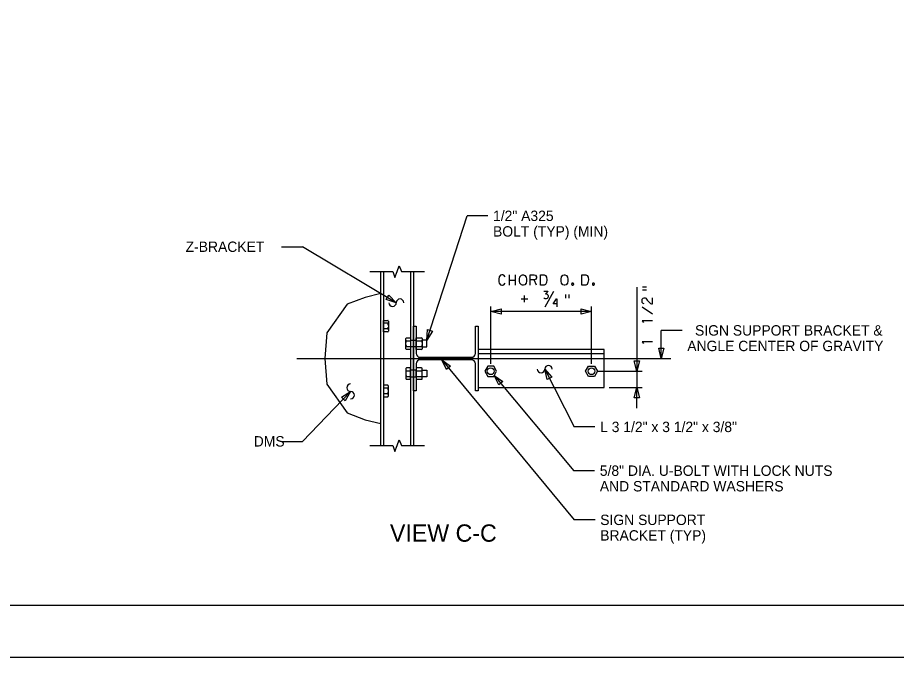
# Model space of a CAD drawing. Extents: x 3831399 to 3833095, y 499014 to 500202.
# Drawn here: x 3832543.5 to 3832797.3, y 499014 to 499198.8 of the extents above; entities that cross this region are included whole.
import ezdxf

# ---------------------------------------------------------------- set-up
doc = ezdxf.new("R2010")
doc.units = 0
for name, color, linetype in [('0-ANCHOR', 7, 'Continuous'), ('2', 7, 'Continuous'), ('CNTR', 7, 'Continuous'), ('Default', 7, 'Continuous'), ('DIM TXT', 7, 'Continuous'), ('PLT-BNDY', 7, 'Continuous'), ('sign', 7, 'Continuous'), ('structure', 7, 'Continuous')]:
    doc.layers.add(name, color=color, linetype=linetype)

msp = doc.modelspace()

# ---------------------------------------------------------------- linework, layer by layer
at = {"layer": '0-ANCHOR'}
for p, q in [((3832649.19, 499108.06), (3832649.19, 499111.38)), ((3832649.19, 499111.38), (3832650.37, 499111.38)), ((3832650.37, 499110.55), (3832649.19, 499110.55)), ((3832650.56, 499111.19), (3832650.56, 499108.25)), ((3832650.37, 499108.89), (3832649.19, 499108.89)), ((3832650.37, 499108.06), (3832649.19, 499108.06)), ((3832655.63, 499103.2), (3832655.63, 499106.15)), ((3832655.82, 499106.34), (3832657, 499106.34)), ((3832655.82, 499105.5), (3832657, 499105.5)), ((3832657, 499106.34), (3832657, 499103.01)), ((3832657, 499105.65), (3832658.59, 499105.65)), ((3832658.59, 499103.01), (3832658.59, 499106.34)), ((3832658.59, 499106.34), (3832660.17, 499106.34)), ((3832658.59, 499105.65), (3832658.59, 499103.7)), ((3832658.59, 499105.5), (3832660.17, 499105.5)), ((3832660.35, 499106.15), (3832660.35, 499103.2)), ((3832661.7, 499105.65), (3832660.35, 499105.65)), ((3832661.7, 499103.7), (3832661.7, 499105.65)), ((3832655.82, 499103.84), (3832657, 499103.84)), ((3832657, 499103.01), (3832655.82, 499103.01)), ((3832658.59, 499103.7), (3832657, 499103.7)), ((3832658.59, 499103.84), (3832660.17, 499103.84)), ((3832660.17, 499103.01), (3832658.59, 499103.01)), ((3832660.35, 499103.7), (3832661.7, 499103.7)), ((3832655.63, 499097.49), (3832655.63, 499094.55)), ((3832657, 499097.68), (3832655.82, 499097.68)), ((3832655.82, 499096.85), (3832657, 499096.85)), ((3832657, 499094.36), (3832657, 499097.68)), ((3832658.59, 499097), (3832657, 499097)), ((3832660.17, 499097.68), (3832658.59, 499097.68)), ((3832658.59, 499097.68), (3832658.59, 499094.36)), ((3832658.59, 499095.04), (3832658.59, 499097)), ((3832658.59, 499096.85), (3832660.17, 499096.85)), ((3832660.35, 499094.55), (3832660.35, 499097.49)), ((3832660.35, 499097), (3832661.7, 499097)), ((3832661.7, 499097), (3832661.7, 499095.04)), ((3832679.26, 499098.17), (3832678.4, 499096.69)), ((3832678.4, 499096.69), (3832679.26, 499095.21)), ((3832680.97, 499098.17), (3832679.26, 499098.17)), ((3832681.82, 499096.69), (3832680.97, 499098.17)), ((3832680.97, 499095.21), (3832681.82, 499096.69)), ((3832707.51, 499096.69), (3832708.36, 499098.17)), ((3832708.36, 499095.21), (3832707.51, 499096.69)), ((3832708.36, 499098.17), (3832710.07, 499098.17)), ((3832710.07, 499098.17), (3832710.92, 499096.69)), ((3832710.92, 499096.69), (3832710.07, 499095.21)), ((3832655.82, 499095.19), (3832657, 499095.19)), ((3832655.82, 499094.36), (3832657, 499094.36)), ((3832657, 499095.04), (3832658.59, 499095.04)), ((3832658.59, 499095.19), (3832660.17, 499095.19)), ((3832658.59, 499094.36), (3832660.17, 499094.36)), ((3832661.7, 499095.04), (3832660.35, 499095.04)), ((3832679.26, 499095.21), (3832680.97, 499095.21)), ((3832710.07, 499095.21), (3832708.36, 499095.21)), ((3832650.37, 499092.63), (3832649.19, 499092.63)), ((3832649.19, 499092.63), (3832649.19, 499089.31)), ((3832650.37, 499091.8), (3832649.19, 499091.8)), ((3832650.56, 499089.5), (3832650.56, 499092.44)), ((3832650.37, 499090.14), (3832649.19, 499090.14)), ((3832649.19, 499089.31), (3832650.37, 499089.31))]:
    msp.add_line(p, q, dxfattribs=at)
for centre in [(3832680.11, 499096.69), (3832709.21, 499096.69)]:
    msp.add_circle(centre, 0.977, dxfattribs=at)
for centre, start, end in [((3832650.37, 499111.19), 360, 90), ((3832650.37, 499110.74), 270, 0), ((3832650.37, 499108.7), 360, 90), ((3832650.37, 499108.25), 270, 0), ((3832655.82, 499106.15), 90, 180), ((3832655.82, 499105.69), 180, 270), ((3832660.17, 499106.15), 360, 90), ((3832660.17, 499105.69), 270, 0), ((3832655.82, 499103.66), 90, 180), ((3832655.82, 499103.2), 180, 270), ((3832660.17, 499103.66), 360, 90), ((3832660.17, 499103.2), 270, 0), ((3832655.82, 499097.49), 90, 180), ((3832655.82, 499097.04), 180, 270), ((3832660.17, 499097.49), 360, 90), ((3832660.17, 499097.04), 270, 0), ((3832655.82, 499095), 90, 180), ((3832655.82, 499094.55), 180, 270), ((3832660.17, 499095), 360, 90), ((3832660.17, 499094.55), 270, 0), ((3832650.37, 499092.44), 360, 90), ((3832650.37, 499091.99), 270, 0), ((3832650.37, 499089.95), 360, 90), ((3832650.37, 499089.5), 270, 0)]:
    msp.add_arc(centre, 0.187, start, end, dxfattribs=at)
for centre, major_axis, start_param, end_param in [((3832650.37, 499110.03), (0, 0.518), 4.712389, 6.283185), ((3832650.37, 499109.41), (0, -0.518), 0, 1.570796), ((3832655.82, 499104.99), (0, 0.518), 0, 1.570796), ((3832655.82, 499104.36), (0, -0.518), 4.712389, 6.283185), ((3832660.17, 499104.99), (0, 0.518), 4.712389, 6.283185), ((3832660.17, 499104.36), (0, -0.518), 0, 1.570796), ((3832655.82, 499096.33), (0, 0.518), 0, 1.570796), ((3832660.17, 499096.33), (0, 0.518), 4.712389, 6.283185), ((3832655.82, 499095.71), (0, -0.518), 4.712389, 6.283185), ((3832660.17, 499095.71), (0, -0.518), 0, 1.570796), ((3832650.37, 499091.28), (0, 0.518), 4.712389, 6.283185), ((3832650.37, 499090.66), (0, -0.518), 0, 1.570796)]:
    msp.add_ellipse(centre, major_axis=major_axis, ratio=0.362172, start_param=start_param, end_param=end_param, dxfattribs=at)
at = {"layer": '2'}
msp.add_line((3833066.16, 499029.03), (3832280.16, 499029.03), dxfattribs=at)
at = {"layer": 'CNTR'}
msp.add_line((3832624.18, 499100.35), (3832732.16, 499100.35), dxfattribs=at)
at = {"layer": 'DIM TXT'}
for p, q in [((3832661.7, 499105.65), (3832673.29, 499141.58)), ((3832679.29, 499141.58), (3832673.29, 499141.58)), ((3832619.75, 499132.65), (3832625.75, 499132.65)), ((3832652.86, 499116.49), (3832625.75, 499132.65)), ((3832653.1, 499125.48), (3832653.72, 499127.17)), ((3832653.72, 499127.17), (3832654.35, 499125.48)), ((3832645.21, 499125.48), (3832651.84, 499125.48)), ((3832651.84, 499125.48), (3832652.47, 499123.79)), ((3832652.47, 499123.79), (3832653.1, 499125.48)), ((3832654.35, 499125.48), (3832660.98, 499125.48)), ((3832685.46, 499124.55), (3832685.46, 499121.55)), ((3832685.46, 499123.04), (3832687.16, 499123.04)), ((3832687.16, 499124.55), (3832687.16, 499121.55)), ((3832693.33, 499121.55), (3832692.64, 499123.08)), ((3832695.82, 499115.33), (3832698.37, 499119.84)), ((3832722.3, 499121.01), (3832722.3, 499096.69)), ((3832725.05, 499121.01), (3832723.98, 499121.01)), ((3832725.05, 499120.06), (3832723.98, 499120.06)), ((3832688.92, 499117.6), (3832690.88, 499117.6)), ((3832689.89, 499116.6), (3832689.89, 499118.59)), ((3832701.79, 499117.83), (3832701.79, 499118.89)), ((3832702.74, 499117.83), (3832702.74, 499118.89)), ((3832680.11, 499098.78), (3832680.11, 499115.43)), ((3832680.11, 499113.93), (3832683.11, 499114.68)), ((3832683.11, 499114.68), (3832683.11, 499113.18)), ((3832706.21, 499114.68), (3832709.21, 499113.93)), ((3832706.21, 499113.18), (3832706.21, 499114.68)), ((3832709.21, 499098.78), (3832709.21, 499115.43)), ((3832726.8, 499113.19), (3832723.8, 499115.15)), ((3832709.21, 499113.93), (3832680.11, 499113.93)), ((3832683.11, 499113.18), (3832680.11, 499113.93)), ((3832709.21, 499113.93), (3832706.21, 499113.18)), ((3832726.8, 499111.21), (3832723.8, 499111.21)), ((3832723.8, 499111.21), (3832724.27, 499110.73)), ((3832729.37, 499100.35), (3832729.37, 499108.49)), ((3832735.37, 499108.49), (3832729.37, 499108.49)), ((3832726.8, 499105.21), (3832723.8, 499105.21)), ((3832723.8, 499105.21), (3832724.27, 499104.73)), ((3832665.98, 499099.99), (3832704.24, 499053.77)), ((3832722.3, 499096.69), (3832721.55, 499099.69)), ((3832721.55, 499099.69), (3832723.05, 499099.69)), ((3832723.05, 499099.69), (3832722.3, 499096.69)), ((3832695.72, 499097.3), (3832704.21, 499080.61)), ((3832710.71, 499096.69), (3832723.8, 499096.69)), ((3832722.3, 499096.69), (3832722.3, 499092)), ((3832681.13, 499095.5), (3832704.12, 499067.97)), ((3832714.33, 499092), (3832723.8, 499092)), ((3832721.55, 499089), (3832722.3, 499092)), ((3832722.3, 499086), (3832722.3, 499092)), ((3832722.3, 499092), (3832723.05, 499089)), ((3832639.67, 499090.86), (3832625.75, 499076.44)), ((3832723.05, 499089), (3832721.55, 499089)), ((3832710.21, 499080.61), (3832704.21, 499080.61)), ((3832619.75, 499076.44), (3832625.75, 499076.44)), ((3832653.1, 499075.21), (3832653.72, 499076.9)), ((3832653.72, 499076.9), (3832654.35, 499075.21)), ((3832645.21, 499075.21), (3832651.84, 499075.21)), ((3832651.84, 499075.21), (3832652.47, 499073.52)), ((3832652.47, 499073.52), (3832653.1, 499075.21)), ((3832654.35, 499075.21), (3832660.98, 499075.21)), ((3832710.12, 499067.97), (3832704.12, 499067.97)), ((3832710.24, 499053.77), (3832704.24, 499053.77))]:
    msp.add_line(p, q, dxfattribs=at)
for points in [[(3832684.33, 499123.96), (3832683.95, 499124.45), (3832683.57, 499124.55), (3832683.31, 499124.55), (3832682.96, 499124.45), (3832682.55, 499123.96), (3832682.46, 499123.3), (3832682.46, 499122.94), (3832682.46, 499122.71), (3832682.48, 499122.49), (3832682.55, 499122.11), (3832682.96, 499121.64), (3832683.31, 499121.55), (3832683.52, 499121.55), (3832683.92, 499121.64), (3832684.33, 499122.11)], [(3832689.31, 499124.55), (3832689.55, 499124.55), (3832689.95, 499124.38), (3832690.33, 499123.89), (3832690.42, 499123.3), (3832690.42, 499122.75), (3832690.33, 499122.16), (3832689.92, 499121.67), (3832689.55, 499121.55), (3832689.31, 499121.55), (3832688.96, 499121.67), (3832688.55, 499122.16), (3832688.46, 499122.75), (3832688.46, 499123.3), (3832688.55, 499123.91), (3832688.96, 499124.41), (3832689.31, 499124.55)], [(3832691.46, 499121.55), (3832691.46, 499124.55), (3832692.66, 499124.55), (3832693.02, 499124.43), (3832693.33, 499123.96), (3832693.33, 499123.67), (3832693.04, 499123.2), (3832692.66, 499123.08), (3832691.46, 499123.08)], [(3832694.46, 499124.55), (3832695.55, 499124.55), (3832695.95, 499124.33), (3832696.21, 499123.82), (3832696.33, 499123.13), (3832696.18, 499122.28), (3832695.92, 499121.76), (3832695.55, 499121.55), (3832694.46, 499121.55), (3832694.46, 499124.55)], [(3832701.31, 499124.55), (3832701.55, 499124.55), (3832701.95, 499124.38), (3832702.33, 499123.89), (3832702.42, 499123.3), (3832702.42, 499122.75), (3832702.33, 499122.16), (3832701.92, 499121.67), (3832701.55, 499121.55), (3832701.31, 499121.55), (3832700.96, 499121.67), (3832700.55, 499122.16), (3832700.46, 499122.75), (3832700.46, 499123.3), (3832700.55, 499123.91), (3832700.96, 499124.41), (3832701.31, 499124.55)], [(3832704.07, 499121.85), (3832704.07, 499121.89), (3832704.07, 499121.92), (3832704.06, 499121.95), (3832704.05, 499121.98), (3832704.03, 499122.01), (3832704.01, 499122.03), (3832703.99, 499122.06), (3832703.97, 499122.08), (3832703.95, 499122.1), (3832703.92, 499122.12), (3832703.89, 499122.13), (3832703.86, 499122.15), (3832703.83, 499122.15), (3832703.8, 499122.16), (3832703.77, 499122.16), (3832703.73, 499122.16), (3832703.7, 499122.15), (3832703.67, 499122.15), (3832703.64, 499122.13), (3832703.61, 499122.12), (3832703.59, 499122.1), (3832703.56, 499122.08), (3832703.54, 499122.06), (3832703.52, 499122.03), (3832703.5, 499122.01), (3832703.49, 499121.98), (3832703.47, 499121.95), (3832703.47, 499121.92), (3832703.46, 499121.89), (3832703.46, 499121.85), (3832703.46, 499121.82), (3832703.47, 499121.79), (3832703.47, 499121.76), (3832703.49, 499121.73), (3832703.5, 499121.7), (3832703.52, 499121.67), (3832703.54, 499121.65), (3832703.56, 499121.63), (3832703.59, 499121.61), (3832703.61, 499121.59), (3832703.64, 499121.57), (3832703.67, 499121.56), (3832703.7, 499121.55), (3832703.73, 499121.55), (3832703.77, 499121.55), (3832703.8, 499121.55), (3832703.83, 499121.55), (3832703.86, 499121.56), (3832703.89, 499121.57), (3832703.92, 499121.59), (3832703.95, 499121.61), (3832703.97, 499121.63), (3832703.99, 499121.65), (3832704.01, 499121.67), (3832704.03, 499121.7), (3832704.05, 499121.73), (3832704.06, 499121.76), (3832704.07, 499121.79), (3832704.07, 499121.82), (3832704.07, 499121.85)], [(3832706.46, 499124.55), (3832707.55, 499124.55), (3832707.95, 499124.33), (3832708.21, 499123.82), (3832708.33, 499123.13), (3832708.18, 499122.28), (3832707.92, 499121.76), (3832707.55, 499121.55), (3832706.46, 499121.55), (3832706.46, 499124.55)], [(3832710.07, 499121.85), (3832710.07, 499121.89), (3832710.07, 499121.92), (3832710.06, 499121.95), (3832710.05, 499121.98), (3832710.03, 499122.01), (3832710.01, 499122.03), (3832709.99, 499122.06), (3832709.97, 499122.08), (3832709.95, 499122.1), (3832709.92, 499122.12), (3832709.89, 499122.13), (3832709.86, 499122.15), (3832709.83, 499122.15), (3832709.8, 499122.16), (3832709.77, 499122.16), (3832709.73, 499122.16), (3832709.7, 499122.15), (3832709.67, 499122.15), (3832709.64, 499122.13), (3832709.61, 499122.12), (3832709.59, 499122.1), (3832709.56, 499122.08), (3832709.54, 499122.06), (3832709.52, 499122.03), (3832709.5, 499122.01), (3832709.49, 499121.98), (3832709.47, 499121.95), (3832709.47, 499121.92), (3832709.46, 499121.89), (3832709.46, 499121.85), (3832709.46, 499121.82), (3832709.47, 499121.79), (3832709.47, 499121.76), (3832709.49, 499121.73), (3832709.5, 499121.7), (3832709.52, 499121.67), (3832709.54, 499121.65), (3832709.56, 499121.63), (3832709.59, 499121.61), (3832709.61, 499121.59), (3832709.64, 499121.57), (3832709.67, 499121.56), (3832709.7, 499121.55), (3832709.73, 499121.55), (3832709.77, 499121.55), (3832709.8, 499121.55), (3832709.83, 499121.55), (3832709.86, 499121.56), (3832709.89, 499121.57), (3832709.92, 499121.59), (3832709.95, 499121.61), (3832709.97, 499121.63), (3832709.99, 499121.65), (3832710.01, 499121.67), (3832710.03, 499121.7), (3832710.05, 499121.73), (3832710.06, 499121.76), (3832710.07, 499121.79), (3832710.07, 499121.82), (3832710.07, 499121.85)], [(3832695.44, 499119.84), (3832696.62, 499119.84), (3832696.55, 499119.58), (3832696.43, 499119.39), (3832696.27, 499119.2), (3832695.91, 499119.04), (3832696.17, 499119.04), (3832696.46, 499118.92), (3832696.62, 499118.73), (3832696.72, 499118.45), (3832696.72, 499118.14), (3832696.62, 499117.86), (3832696.43, 499117.67), (3832696.17, 499117.6), (3832695.86, 499117.6), (3832695.61, 499117.67), (3832695.44, 499117.86)], [(3832699.38, 499116.11), (3832698.11, 499116.11), (3832698.11, 499116.2), (3832699.1, 499117.57), (3832699.22, 499117.57), (3832699.22, 499115.33)], [(3832724.41, 499116.19), (3832724.13, 499116.28), (3832723.89, 499116.54), (3832723.8, 499116.9), (3832723.8, 499117.16), (3832723.89, 499117.51), (3832724.15, 499117.77), (3832724.41, 499117.89), (3832724.67, 499117.89), (3832724.88, 499117.8), (3832725.33, 499117.21), (3832726.28, 499116.28), (3832726.51, 499116.19), (3832726.8, 499116.19), (3832726.8, 499117.89)]]:
    msp.add_lwpolyline(points, dxfattribs=at)
for points in [[(3832650.66, 499118.67), (3832652.86, 499116.49), (3832649.9, 499117.38)], [(3832663.34, 499108.28), (3832661.7, 499105.65), (3832661.91, 499108.74)], [(3832730.12, 499103.35), (3832729.37, 499100.35), (3832728.62, 499103.35)], [(3832667.32, 499097.2), (3832665.98, 499099.99), (3832668.48, 499098.15)], [(3832696.41, 499094.29), (3832695.72, 499097.3), (3832697.75, 499094.97)], [(3832682.48, 499092.72), (3832681.13, 499095.5), (3832683.63, 499093.68)], [(3832637.05, 499089.22), (3832639.67, 499090.86), (3832638.13, 499088.18)]]:
    msp.add_lwpolyline(points, close=True, dxfattribs=at)
for centre, start, end in [((3832653.93, 499116.49), 0, 180), ((3832651.78, 499116.49), 180, 0), ((3832694.64, 499097.3), 180, 0), ((3832696.79, 499097.3), 0, 180), ((3832639.67, 499091.93), 90, 270), ((3832639.67, 499089.78), 270, 90)]:
    msp.add_arc(centre, 1.08, start, end, dxfattribs=at)
at = {"layer": 'PLT-BNDY'}
msp.add_lwpolyline([(3832240.16, 499608.03), (3833081.16, 499608.03), (3833081.16, 499014.03), (3832240.16, 499014.03)], close=True, dxfattribs=at)
at = {"layer": 'sign'}
for p, q in [((3832648.41, 499075.21), (3832648.41, 499125.48)), ((3832649.19, 499125.48), (3832649.19, 499075.21)), ((3832657, 499125.48), (3832657, 499075.21)), ((3832657.78, 499125.48), (3832657.78, 499075.21))]:
    msp.add_line(p, q, dxfattribs=at)
for points in [[(3832648.41, 499119.1), (3832643.9, 499118.02), (3832638.7, 499116.05), (3832632.83, 499107.76), (3832632.2, 499100.35)], [(3832632.2, 499100.35), (3832632.83, 499092.94), (3832638.7, 499084.64), (3832643.9, 499082.67), (3832648.41, 499081.6)]]:
    msp.add_lwpolyline(points, dxfattribs=at)
at = {"layer": 'structure'}
for p, q in [((3832712.83, 499102.94), (3832676.5, 499102.94)), ((3832676.5, 499102.94), (3832676.5, 499092)), ((3832712.83, 499102.94), (3832676.5, 499102.94)), ((3832676.5, 499102.94), (3832676.5, 499101.77)), ((3832676.5, 499101.77), (3832712.83, 499101.77)), ((3832712.83, 499092), (3832712.83, 499102.94)), ((3832712.83, 499101.77), (3832712.83, 499102.94)), ((3832676.5, 499092), (3832712.83, 499092))]:
    msp.add_line(p, q, dxfattribs=at)
for points in [[(3832658.59, 499098.85), (3832658.59, 499090.99), (3832657.78, 499090.99), (3832657.78, 499109.71), (3832658.59, 499109.71), (3832658.59, 499101.85)], [(3832676.5, 499109.71), (3832676.5, 499090.99), (3832675.69, 499090.99), (3832675.69, 499098.85)], [(3832675.69, 499101.85), (3832675.69, 499109.71), (3832676.5, 499109.71)], [(3832659.74, 499100.71), (3832674.55, 499100.71)], [(3832674.55, 499099.99), (3832659.74, 499099.99)]]:
    msp.add_lwpolyline(points, dxfattribs=at)
for centre, start, end in [((3832659.74, 499101.85), 180, 270), ((3832674.55, 499101.85), 270, 360), ((3832659.74, 499098.85), 90, 180), ((3832674.55, 499098.85), 0, 90)]:
    msp.add_arc(centre, 1.14, start, end, dxfattribs=at)

# ---------------------------------------------------------------- texts
at = {"layer": 'Default'}
msp.add_text('VIEW C-C', height=5, dxfattribs=at).set_placement((3832651.03, 499047.45))
at = {"layer": 'DIM TXT'}
for s, height, p in [('1/2" A325', 3, (3832680.79, 499140.08)), ('BOLT (TYP) (MIN)', 2.9999, (3832680.79, 499135.58)), ('Z-BRACKET', 3, (3832592.03, 499131.15)), ('  SIGN SUPPORT BRACKET &', 2.9999, (3832736.87, 499106.99)), ('ANGLE CENTER OF GRAVITY', 2.9999, (3832736.87, 499102.49)), ('L 3 1/2" x 3 1/2" x 3/8"', 2.9999, (3832711.71, 499079.11)), ('DMS', 3, (3832611.7, 499074.94)), ('5/8" DIA. U-BOLT WITH LOCK NUTS', 2.9999, (3832711.62, 499066.47)), ('AND STANDARD WASHERS', 2.9999, (3832711.62, 499061.97)), ('SIGN SUPPORT', 2.9999, (3832711.74, 499052.27)), ('BRACKET (TYP)', 2.9999, (3832711.74, 499047.77))]:
    msp.add_text(s, height=height, dxfattribs=at).set_placement(p)

doc.saveas('drawing.dxf')
